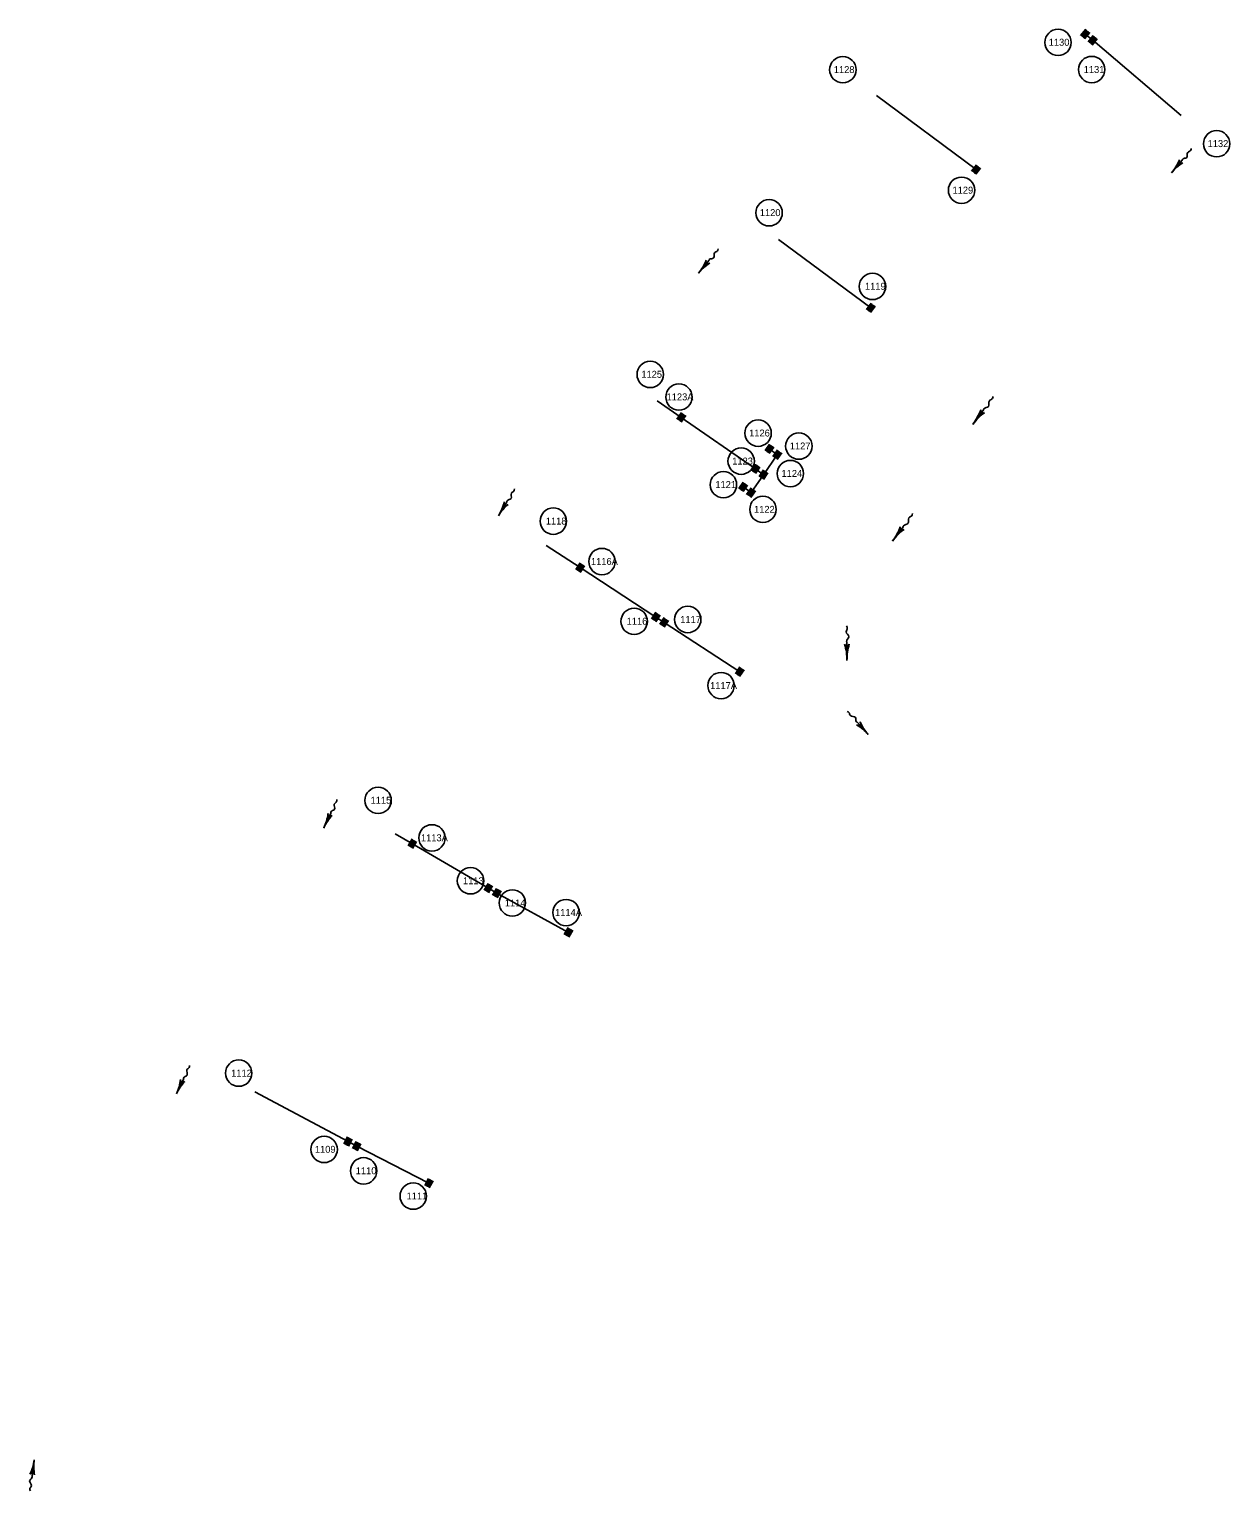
# Model space of a CAD drawing. Extents: x 594534 to 598564, y 225861 to 236229.
# Drawn here: x 594785 to 595822, y 228676 to 229938 of the extents above; entities that cross this region are included whole.
import ezdxf

# ---------------------------------------------------------------- set-up
doc = ezdxf.new("R2010")
doc.units = 0
for name, color, linetype in [('P_DRN_Flow', 7, 'Continuous'), ('P_DRN_Inlet', 7, 'Continuous'), ('P_DRN_SS_UG', 7, 'Continuous'), ('P_DRN_Text', 7, 'Continuous')]:
    doc.layers.add(name, color=color, linetype=linetype)

msp = doc.modelspace()

# ---------------------------------------------------------------- linework, layer by layer
at = {"layer": 'P_DRN_Flow'}
for p, q in [((595771.8, 229814.5), (595780.9, 229825.3)), ((595363.3, 229727.8), (595372.3, 229738.7)), ((595600.2, 229597.3), (595609.5, 229609.8)), ((595190.6, 229518.3), (595197.9, 229530.3)), ((595530.9, 229496.5), (595540.1, 229508.8)), ((595491.5, 229393.4), (595491.5, 229409)), ((595510, 229329.5), (595500.5, 229340)), ((595039.8, 229248.8), (595045.8, 229261.5)), ((594912.5, 229019.2), (594918.5, 229032)), ((594789.8, 228703.3), (594787.9, 228689.3))]:
    msp.add_line(p, q, dxfattribs=at)
for points in [[(595778.5, 229825.6), (595778, 229821.9), (595781.6, 229823)], [(595370, 229738.9), (595369.4, 229735.2), (595373, 229736.4)], [(595607.1, 229609.8), (595606.6, 229605.8), (595610.3, 229607.4)], [(595195.5, 229530.2), (595195.6, 229526.5), (595199, 229528.2)], [(595537.6, 229508.9), (595537.1, 229504.9), (595540.8, 229506.5)], [(595489.5, 229407.5), (595491.5, 229404), (595493.5, 229407.6)], [(595499.9, 229337.7), (595503.6, 229336.7), (595502.9, 229340.4)], [(595043.4, 229261.2), (595043.8, 229257.4), (595047, 229259.5)], [(594916.1, 229031.6), (594916.6, 229027.9), (594919.8, 229029.9)], [(594790, 228690.3), (594788.5, 228693.8), (594786.1, 228690.9)]]:
    msp.add_lwpolyline(points, dxfattribs=at)
for centre, start, end in [((595739.7, 229841.4), 320.0425, 337.8048), ((595804, 229787.6), 122.2801, 140.0425), ((595331.1, 229754.8), 320.0425, 337.8048), ((595395.4, 229700.9), 122.2801, 140.0425), ((595154.8, 229540.2), 328.5278, 346.2901), ((595226.4, 229496.4), 130.7655, 148.5278), ((595541.1, 229357.6), 204.2985, 222.0608), ((595478.8, 229301.4), 42.0608, 59.8232), ((595001.8, 229266.6), 334.7829, 352.5452), ((595077.7, 229230.9), 137.0206, 154.7829), ((594874.5, 229037.1), 334.7829, 352.5452), ((594950.5, 229001.3), 137.0206, 154.7829), ((594748.2, 228709), 334.3197, 352.082), ((594831.4, 228697.5), 172.082, 189.8443)]:
    msp.add_arc(centre, 42, start, end, dxfattribs=at)
for centre, major_axis, ratio, start_param, end_param in [((595566.6, 229622.4), (27.6, 37.1), 0.907641, 4.712389, 5.0224), ((595633.9, 229572.2), (-27.6, -37.1), 0.907641, 4.402378, 4.712389), ((595497.3, 229521.6), (27.3, 36.5), 0.920446, 4.712389, 5.0224), ((595564.5, 229471.5), (-27.3, -36.5), 0.920446, 4.402378, 4.712389), ((595449.6, 229393.3), (-0.1, 46.2), 0.907641, 4.712389, 5.0224), ((595533.5, 229393.5), (0.1, -46.2), 0.907641, 4.402378, 4.712389)]:
    msp.add_ellipse(centre, major_axis=major_axis, ratio=ratio, start_param=start_param, end_param=end_param, dxfattribs=at)
for points in [[(595780.9, 229825.3), (595781.2, 229826.1), (595784.9, 229827.7), (595785.8, 229832.1), (595788.3, 229833.7), (595788.9, 229835.4)], [(595372.3, 229738.7), (595372.6, 229739.5), (595376.4, 229741), (595377.2, 229745.5), (595379.7, 229747), (595380.4, 229748.7)], [(595609.5, 229609.8), (595609.8, 229610.7), (595613.7, 229612.7), (595614.5, 229617.5), (595617.1, 229619.5), (595617.8, 229621.4)], [(595197.9, 229530.3), (595198.1, 229531.2), (595201.6, 229533.3), (595201.8, 229537.8), (595204, 229539.7), (595204.4, 229541.5)], [(595540.1, 229508.8), (595540.4, 229509.7), (595544.2, 229511.7), (595545, 229516.5), (595547.6, 229518.4), (595548.2, 229520.2)], [(595491.5, 229409), (595491.2, 229409.9), (595493.1, 229413.9), (595490.9, 229418.2), (595491.8, 229421.3), (595491.2, 229423.2)], [(595500.5, 229340), (595499.8, 229340.4), (595498.8, 229344.3), (595494.5, 229345.8), (595493.3, 229348.5), (595491.7, 229349.4)], [(595045.8, 229261.5), (595045.8, 229262.4), (595049.1, 229264.9), (595048.8, 229269.3), (595050.8, 229271.5), (595051, 229273.3)], [(594918.5, 229032), (594918.6, 229032.8), (594921.8, 229035.3), (594921.5, 229039.8), (594923.5, 229042), (594923.7, 229043.8)], [(594787.9, 228689.3), (594788.1, 228688.5), (594785.7, 228685.1), (594787.3, 228680.9), (594786, 228678.3), (594786.4, 228676.5)]]:
    msp.add_spline(points, degree=3, dxfattribs=at)
at = {"layer": 'P_DRN_Inlet'}
for p, q in [((595693.3, 229933.1), (595697.7, 229938.4)), ((595694, 229932.5), (595698.4, 229937.8)), ((595694.7, 229931.9), (595699.1, 229937.2)), ((595695.4, 229931.4), (595699.8, 229936.7)), ((595696.1, 229930.8), (595700.5, 229936.1)), ((595696.8, 229930.2), (595701.2, 229935.5)), ((595699.9, 229927.7), (595704.3, 229933)), ((595700.6, 229927.1), (595705, 229932.4)), ((595701.3, 229926.5), (595705.7, 229931.8)), ((595702, 229925.9), (595706.4, 229931.2)), ((595702.7, 229925.4), (595707, 229930.7)), ((595703.3, 229924.8), (595707.7, 229930.1)), ((595599.2, 229816), (595603.4, 229821.4)), ((595599.9, 229815.4), (595604.1, 229820.8)), ((595600.6, 229814.9), (595604.8, 229820.3)), ((595601.3, 229814.3), (595605.5, 229819.7)), ((595602, 229813.7), (595606.3, 229819.2)), ((595602.7, 229813.2), (595607, 229818.6)), ((595508.3, 229696.4), (595512.4, 229702)), ((595509.1, 229695.9), (595513.1, 229701.5)), ((595509.8, 229695.4), (595513.9, 229700.9)), ((595510.5, 229694.8), (595514.6, 229700.4)), ((595511.2, 229694.3), (595515.3, 229699.9)), ((595512, 229693.8), (595516, 229699.3)), ((595344.7, 229601.8), (595348.6, 229607.4)), ((595345.4, 229601.3), (595349.4, 229606.9)), ((595346.2, 229600.8), (595350.1, 229606.4)), ((595346.9, 229600.2), (595350.8, 229605.9)), ((595347.6, 229599.7), (595351.6, 229605.4)), ((595348.4, 229599.2), (595352.3, 229604.9)), ((595412.6, 229558.9), (595348.5, 229603.3)), ((595420.8, 229574.6), (595424.7, 229580.2)), ((595421.5, 229574.1), (595425.5, 229579.7)), ((595422.3, 229573.5), (595426.2, 229579.2)), ((595423, 229573), (595426.9, 229578.7)), ((595423.7, 229572.5), (595427.7, 229578.1)), ((595424.5, 229572), (595428.4, 229577.6)), ((595424.6, 229576.1), (595431.4, 229571)), ((595427.6, 229569.5), (595431.5, 229575.2)), ((595428.4, 229569), (595432.2, 229574.6)), ((595429.1, 229568.5), (595433, 229574.1)), ((595429.9, 229568), (595433.7, 229573.6)), ((595430.6, 229567.4), (595434.5, 229573.1)), ((595431.4, 229566.9), (595435.2, 229572.6)), ((595408.8, 229557.3), (595412.7, 229563)), ((595409.6, 229556.8), (595413.4, 229562.5)), ((595410.3, 229556.3), (595414.2, 229562)), ((595411, 229555.8), (595414.9, 229561.5)), ((595411.8, 229555.3), (595415.7, 229561)), ((595412.5, 229554.8), (595416.4, 229560.4)), ((595412.6, 229558.9), (595419.4, 229553.8)), ((595415.6, 229552.3), (595419.5, 229557.9)), ((595416.4, 229551.7), (595420.3, 229557.4)), ((595417.1, 229551.2), (595421, 229556.9)), ((595417.9, 229550.7), (595421.8, 229556.4)), ((595418.6, 229550.2), (595422.5, 229555.9)), ((595419.4, 229549.7), (595423.2, 229555.4)), ((595398.1, 229541.8), (595401.9, 229547.4)), ((595398.8, 229541.3), (595402.7, 229546.9)), ((595399.6, 229540.7), (595403.4, 229546.4)), ((595400.3, 229540.2), (595404.2, 229545.9)), ((595401.1, 229539.7), (595404.9, 229545.4)), ((595401.8, 229539.2), (595405.7, 229544.9)), ((595401.9, 229543.3), (595408.7, 229538.3)), ((595404.9, 229536.7), (595408.8, 229542.4)), ((595405.7, 229536.2), (595409.5, 229541.9)), ((595406.4, 229535.7), (595410.3, 229541.4)), ((595407.1, 229535.2), (595411, 229540.9)), ((595407.9, 229534.7), (595411.8, 229540.4)), ((595408.6, 229534.2), (595412.5, 229539.9)), ((595257.4, 229471.9), (595261.2, 229477.7)), ((595258.2, 229471.4), (595262, 229477.2)), ((595258.9, 229470.9), (595262.7, 229476.7)), ((595259.7, 229470.4), (595263.5, 229476.2)), ((595260.4, 229469.9), (595264.2, 229475.7)), ((595261.2, 229469.5), (595265, 229475.2)), ((595322.8, 229429.3), (595326.5, 229435)), ((595323.5, 229428.8), (595327.3, 229434.5)), ((595324.3, 229428.3), (595328, 229434)), ((595325, 229427.8), (595328.8, 229433.5)), ((595325.8, 229427.3), (595329.5, 229433)), ((595326.5, 229426.8), (595330.3, 229432.6)), ((595329.9, 229424.7), (595333.7, 229430.4)), ((595330.6, 229424.2), (595334.4, 229429.9)), ((595331.4, 229423.7), (595335.2, 229429.4)), ((595332.1, 229423.2), (595335.9, 229428.9)), ((595332.9, 229422.7), (595336.7, 229428.4)), ((595333.6, 229422.2), (595337.4, 229427.9)), ((595395.2, 229382), (595399, 229387.8)), ((595395.9, 229381.5), (595399.7, 229387.3)), ((595396.7, 229381), (595400.5, 229386.8)), ((595397.4, 229380.5), (595401.2, 229386.3)), ((595398.2, 229380), (595402, 229385.8)), ((595398.9, 229379.5), (595402.7, 229385.3)), ((595112.6, 229233.3), (595116.1, 229239.3)), ((595113.4, 229232.9), (595116.8, 229238.8)), ((595114.1, 229232.4), (595117.6, 229238.3)), ((595114.9, 229232), (595118.4, 229237.9)), ((595115.7, 229231.5), (595119.2, 229237.4)), ((595116.5, 229231), (595119.9, 229237)), ((595178.2, 229195), (595181.7, 229200.9)), ((595179, 229194.5), (595182.5, 229200.5)), ((595179.8, 229194.1), (595183.3, 229200)), ((595180.5, 229193.6), (595184, 229199.6)), ((595181.3, 229193.2), (595184.8, 229199.1)), ((595182.1, 229192.7), (595185.6, 229198.7)), ((595185.6, 229190.7), (595189, 229196.6)), ((595186.3, 229190.3), (595189.8, 229196.2)), ((595187.1, 229189.8), (595190.6, 229195.7)), ((595187.9, 229189.3), (595191.4, 229195.3)), ((595188.7, 229188.9), (595192.1, 229194.8)), ((595189.4, 229188.4), (595192.9, 229194.4)), ((595247.4, 229156.8), (595250.9, 229162.7)), ((595248.2, 229156.3), (595251.7, 229162.3)), ((595249, 229155.9), (595252.5, 229161.8)), ((595249.8, 229155.4), (595253.3, 229161.3)), ((595250.5, 229155), (595254, 229160.9)), ((595251.3, 229154.5), (595254.8, 229160.4)), ((595057.1, 228975.9), (595060.2, 228982.1)), ((595057.9, 228975.5), (595061, 228981.7)), ((595058.7, 228975.1), (595061.8, 228981.3)), ((595059.5, 228974.7), (595062.6, 228980.9)), ((595060.3, 228974.3), (595063.4, 228980.5)), ((595061.1, 228973.9), (595064.2, 228980)), ((595064.6, 228972.1), (595067.8, 228978.1)), ((595065.4, 228971.6), (595068.6, 228977.7)), ((595066.2, 228971.2), (595069.4, 228977.3)), ((595067, 228970.8), (595070.2, 228976.9)), ((595067.8, 228970.4), (595071, 228976.5)), ((595068.6, 228970), (595071.8, 228976)), ((595126.9, 228940.2), (595130.2, 228946.2)), ((595127.7, 228939.8), (595130.9, 228945.8)), ((595128.5, 228939.3), (595131.7, 228945.4)), ((595129.3, 228938.9), (595132.5, 228944.9)), ((595130.1, 228938.5), (595133.3, 228944.5)), ((595130.8, 228938), (595134.1, 228944.1))]:
    msp.add_line(p, q, dxfattribs=at)
for points in [[(595697.4, 229932.9), (595698.7, 229934.4), (595697.1, 229935.7), (595695.9, 229934.2)], [(595703.9, 229927.5), (595705.2, 229929), (595703.7, 229930.3), (595702.4, 229928.7)], [(595603.2, 229815.9), (595604.5, 229817.5), (595602.9, 229818.7), (595601.7, 229817.1)], [(595512.4, 229696.5), (595513.6, 229698.1), (595512, 229699.3), (595510.8, 229697.7)], [(595348.8, 229601.9), (595349.9, 229603.6), (595348.3, 229604.7), (595347.1, 229603.1)], [(595424.8, 229574.7), (595426, 229576.4), (595424.3, 229577.5), (595423.2, 229575.9)], [(595431.7, 229569.7), (595432.8, 229571.3), (595431.2, 229572.4), (595430, 229570.8)], [(595412.9, 229557.5), (595414, 229559.1), (595412.3, 229560.3), (595411.2, 229558.6)], [(595419.7, 229552.4), (595420.8, 229554.1), (595419.2, 229555.2), (595418.1, 229553.6)], [(595402.1, 229541.9), (595403.3, 229543.6), (595401.6, 229544.7), (595400.5, 229543.1)], [(595409, 229536.9), (595410.1, 229538.5), (595408.4, 229539.7), (595407.3, 229538)], [(595261.5, 229472.2), (595262.6, 229473.8), (595260.9, 229474.9), (595259.8, 229473.3)], [(595326.8, 229429.5), (595327.9, 229431.2), (595326.2, 229432.3), (595325.1, 229430.6)], [(595333.9, 229424.9), (595335, 229426.6), (595333.4, 229427.7), (595332.3, 229426)], [(595399.2, 229382.3), (595400.3, 229383.9), (595398.7, 229385), (595397.6, 229383.4)], [(595116.6, 229233.8), (595117.6, 229235.5), (595115.9, 229236.5), (595114.9, 229234.8)], [(595182.3, 229195.5), (595183.3, 229197.2), (595181.5, 229198.2), (595180.5, 229196.5)], [(595189.6, 229191.2), (595190.6, 229192.9), (595188.9, 229193.9), (595187.9, 229192.2)], [(595251.5, 229157.2), (595252.5, 229159), (595250.8, 229160), (595249.8, 229158.3)], [(595061.1, 228976.7), (595062, 228978.4), (595060.2, 228979.3), (595059.3, 228977.6)], [(595068.6, 228972.7), (595069.5, 228974.5), (595067.8, 228975.4), (595066.8, 228973.6)], [(595130.9, 228940.8), (595131.9, 228942.5), (595130.1, 228943.5), (595129.1, 228941.7)]]:
    msp.add_lwpolyline(points, close=True, dxfattribs=at)
for points in [[(595697.3, 229934.3), (595703.8, 229928.9)], [(595326.5, 229430.9), (595333.6, 229426.3)]]:
    msp.add_lwpolyline(points, dxfattribs=at)
at = {"layer": 'P_DRN_SS_UG'}
for p, q in [((595703.8, 229928.9), (595780.2, 229864.1)), ((595603.1, 229817.3), (595517, 229881.2)), ((595512.2, 229697.9), (595432.4, 229757)), ((595348.5, 229603.3), (595327.7, 229617.7)), ((595431.4, 229571), (595419.4, 229553.8)), ((595408.7, 229538.3), (595419.4, 229553.8)), ((595261.2, 229473.6), (595231.7, 229492.8)), ((595326.5, 229430.9), (595261.2, 229473.6)), ((595399, 229383.7), (595333.6, 229426.3)), ((595116.3, 229235.1), (595101.4, 229243.8)), ((595181.9, 229196.8), (595116.3, 229235.1)), ((595251.1, 229158.6), (595189.2, 229192.5)), ((595060.7, 228978), (594980.1, 229020.9)), ((595060.7, 228978), (595068.2, 228974)), ((595130.5, 228942.1), (595068.2, 228974))]:
    msp.add_line(p, q, dxfattribs=at)
msp.add_lwpolyline([(595181.9, 229196.8), (595189.2, 229192.5)], dxfattribs=at)
at = {"layer": 'P_DRN_Text'}
for centre in [(595673.8, 229927.1), (595488, 229903.5), (595702.9, 229903.6), (595810.8, 229839.6), (595590.5, 229799.4), (595424.3, 229780), (595513.6, 229716.4), (595321.7, 229640.4), (595346.5, 229620.9), (595414.8, 229589.7), (595450, 229578.5), (595400.2, 229565.5), (595384.9, 229545.2), (595442.7, 229554.8), (595419, 229523.9), (595238, 229513.7), (595280, 229478.8), (595354.1, 229428.8), (595307.8, 229427.2), (595382.8, 229371.7), (595086.7, 229272.6), (595133.2, 229240.2), (595166.5, 229203.2), (595202.6, 229184), (595249, 229175.7), (594966.3, 229037.1), (595040.1, 228971.2), (595074.2, 228952.7), (595117, 228930.9)]:
    msp.add_circle(centre, 11.4, dxfattribs=at)

# ---------------------------------------------------------------- texts
for s, p in [('1130', (595665.8, 229924.2)), ('1128', (595480.2, 229900.6)), ('1131', (595696, 229900.7)), ('1132', (595803, 229836.7)), ('1129', (595582.7, 229796.5)), ('1120', (595416.3, 229777.1)), ('1119', (595507.1, 229713.5)), ('1125', (595314, 229637.5)), ('1123A', (595335.8, 229618)), ('1126', (595407.1, 229586.8)), ('1127', (595442.2, 229575.6)), ('1123', (595392.5, 229562.6)), ('1124', (595435, 229551.9)), ('1121', (595377.9, 229542.3)), ('1118', (595231.5, 229510.8)), ('1122', (595411.3, 229520.9)), ('1116A', (595270.5, 229475.9)), ('1116', (595301.3, 229424.3)), ('1117', (595347.6, 229425.8)), ('1117A', (595373.4, 229368.7)), ('1115', (595080.2, 229269.7)), ('1113A', (595123.7, 229237.3)), ('1113', (595160, 229200.2)), ('1114', (595196.1, 229181)), ('1114A', (595239.5, 229172.8)), ('1112', (594959.8, 229034.1)), ('1109', (595032.1, 228968.3)), ('1110', (595067.4, 228949.8)), ('1111', (595111.3, 228928))]:
    msp.add_text(s, height=6, dxfattribs=at).set_placement(p)

doc.saveas('drawing.dxf')
